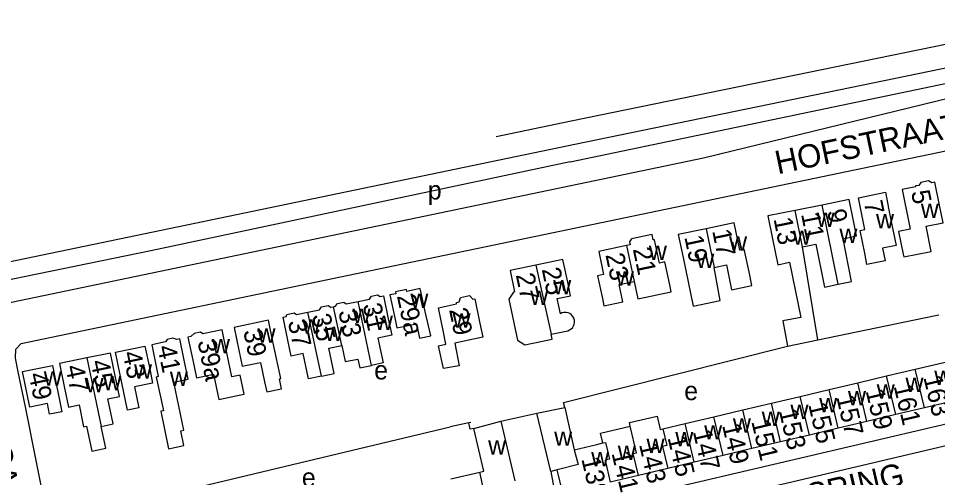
# Model space of a CAD drawing. Extents: x 163026 to 166241, y 382475 to 384501.
# Drawn here: x 164035.2 to 164232.4, y 384127.8 to 384226.4 of the extents above; entities that cross this region are included whole.
import ezdxf

# ---------------------------------------------------------------- set-up
doc = ezdxf.new("R2010")
doc.units = 0
for name, color, linetype in [('BLT_Basislijn', 7, 'Continuous'), ('BLT_Bebouwing', 7, 'Continuous'), ('BLT_Centroide', 7, 'Continuous'), ('BLT_Huisnummer', 7, 'Continuous'), ('BLT_Huisnummer_ tussenligend', 7, 'Continuous'), ('BLT_Onderverdeling_panden', 7, 'Continuous'), ('BLT_Spoorlijn', 7, 'Continuous'), ('BLT_Straatnaam', 7, 'Continuous')]:
    doc.layers.add(name, color=color, linetype=linetype)

msp = doc.modelspace()

# ---------------------------------------------------------------- linework, layer by layer
at = {"layer": 'BLT_Basislijn'}
for p, q in [((164152.1, 384143.91), (164200.2, 384156.04)), ((164152.39, 384142.84), (164152.1, 384143.91)), ((164138.72, 384139.93), (164146.41, 384141.66)), ((164041.64, 384118.16), (164127.83, 384138.74)), ((164151.07, 384119.92), (164236.93, 384140.04)), ((164149.43, 384129.14), (164151.07, 384119.92))]:
    msp.add_line(p, q, dxfattribs=at)
for points in [[(164153.55, 384195.58), (164243.98, 384214.46), (164247.92, 384214.05), (164263.66, 384217.55)], [(163900.11, 384137.3), (163905.37, 384138.71), (164182.17, 384196.48), (164249.9, 384212.98), (164253.88, 384212.82), (164257.32, 384211.62), (164261.05, 384208.36), (164262.81, 384205.4), (164265.99, 384192.34), (164268.94, 384175.29), (164269.89, 384164.18), (164270.1, 384149.11), (164272.14, 384146.86), (164275.23, 384146.44), (164277.11, 384147)], [(164041.64, 384118.16), (164036.68, 384143.01), (164035.15, 384150.54), (164034.58, 384153.44), (164034.61, 384155.37), (164035.79, 384156.58), (164112.52, 384172.6), (164235.89, 384198.32), (164241.09, 384199.14)], [(164153.55, 384195.58), (164063.6, 384176.49), (163969.43, 384157.19)], [(164206.72, 384157.42), (164231.95, 384162.6), (164232.65, 384162.76)], [(164046.47, 384095.37), (164046.9, 384094.29), (164048.09, 384092.84), (164049.85, 384092.25), (164052.21, 384092.19), (164083.95, 384099.3), (164253.63, 384139.27), (164258.18, 384142.14), (164259.86, 384145.55)], [(164132.89, 384138.36), (164132.12, 384138.19), (164131.84, 384139.58)]]:
    msp.add_lwpolyline(points, dxfattribs=at)
at = {"layer": 'BLT_Bebouwing'}
for p, q in [((164207.64, 384186.31), (164201.83, 384185.15)), ((164206.72, 384157.42), (164203.4, 384177.34)), ((164200.2, 384156.04), (164206.72, 384157.42)), ((164227.62, 384151.09), (164234.7, 384152.76)), ((164221.45, 384149.63), (164227.62, 384151.09)), ((164215.28, 384148.17), (164221.45, 384149.63)), ((164202.93, 384145.26), (164209.11, 384146.71)), ((164209.11, 384146.71), (164215.28, 384148.17)), ((164196.76, 384143.8), (164202.93, 384145.26)), ((164146.41, 384141.66), (164152.39, 384142.84)), ((164152.39, 384142.84), (164154.43, 384133.8)), ((164190.59, 384142.34), (164196.76, 384143.8)), ((164229.59, 384142.78), (164223.41, 384141.33)), ((164235.76, 384144.24), (164229.59, 384142.78)), ((164149.43, 384129.14), (164146.41, 384141.66)), ((164178.24, 384139.42), (164184.41, 384140.88)), ((164184.41, 384140.88), (164190.59, 384142.34)), ((164223.41, 384141.33), (164217.24, 384139.87)), ((164131.84, 384139.58), (164127.83, 384138.74)), ((164132.23, 384139.66), (164131.84, 384139.58)), ((164132.89, 384138.36), (164138.72, 384139.93)), ((164138.72, 384139.93), (164141.67, 384127.16)), ((164173.43, 384138.29), (164178.24, 384139.42)), ((164217.24, 384139.87), (164211.07, 384138.41)), ((164204.89, 384136.95), (164198.72, 384135.49)), ((164211.07, 384138.41), (164204.89, 384136.95)), ((164198.72, 384135.49), (164192.55, 384134.04)), ((164192.55, 384134.04), (164186.37, 384132.58)), ((164180.2, 384131.12), (164174.49, 384129.77)), ((164186.37, 384132.58), (164180.2, 384131.12)), ((164127.98, 384127.55), (164134.19, 384129.02)), ((164150.77, 384129.49), (164149.43, 384129.14)), ((164174.49, 384129.77), (164168.21, 384128.29)), ((164168.21, 384128.29), (164162.18, 384126.86))]:
    msp.add_line(p, q, dxfattribs=at)
for points in [[(164232.8, 384186.31), (164231.82, 384191.21), (164231.15, 384191.08), (164230.47, 384191.53), (164228.78, 384191.19), (164228.35, 384190.54), (164227.65, 384190.41), (164227.69, 384190.23), (164224.81, 384189.66), (164226.52, 384181.16), (164224.03, 384180.67), (164225.02, 384175.77), (164225.13, 384175.2), (164231.02, 384176.38), (164229.94, 384181.8), (164233.56, 384182.52), (164232.8, 384186.31)], [(164222.18, 384184.15), (164222.94, 384180.36), (164223.49, 384177.63), (164220.57, 384177.04), (164221.12, 384174.35), (164217.24, 384173.57), (164216.76, 384175.97), (164215.78, 384180.88), (164216.81, 384181.08), (164215.45, 384187.89), (164221.2, 384189.05), (164222.18, 384184.15)], [(164211.05, 384169.3), (164213.96, 384169.89), (164212.11, 384179.1), (164215.02, 384179.68), (164214.44, 384182.57), (164213.46, 384187.48), (164207.64, 384186.31)], [(164201.83, 384185.15), (164195.99, 384183.98), (164196.99, 384179.04), (164198.09, 384173.51), (164200.65, 384174.03), (164203.02, 384162.18), (164199.19, 384161.47), (164200.2, 384156.04)], [(164184.49, 384172.93), (164187.09, 384173.47), (164188.21, 384168.11), (164192.56, 384169.02), (164191.94, 384171.96), (164190.92, 384176.86), (164189.97, 384176.66), (164188.75, 384182.48), (164182.76, 384181.22)], [(164182.76, 384181.22), (164176.76, 384179.97), (164177.78, 384175.09), (164179.96, 384164.64), (164185.77, 384165.85), (164184.49, 384172.93)], [(164167.28, 384169.94), (164168.06, 384166.2), (164175.24, 384167.7), (164174.92, 384169.22), (164173.9, 384174.11), (164172.71, 384173.87), (164171.67, 384178.87), (164171.4, 384178.82), (164171.16, 384179.98), (164166.69, 384179.05), (164166.32, 384178.41), (164166.45, 384177.78), (164165.67, 384177.62)], [(164165.67, 384177.62), (164159.68, 384176.37), (164160.72, 384171.39), (164159.46, 384171.12), (164160.48, 384166.23), (164160.8, 384164.69), (164164.87, 384165.54), (164164.09, 384169.27), (164167.28, 384169.94)], [(164203.4, 384177.34), (164206.3, 384177.92), (164208.14, 384168.72), (164211.05, 384169.3)], [(164149.45, 384158.61), (164153.04, 384159.35), (164153.45, 384159.52), (164153.76, 384159.73), (164154.03, 384159.99), (164154.27, 384160.36), (164154.42, 384160.74), (164154.49, 384161.19), (164154.47, 384161.62), (164154.33, 384162.07), (164154.13, 384162.43), (164153.82, 384162.78), (164153.49, 384163.02), (164153.12, 384163.18), (164152.68, 384163.27), (164152.23, 384163.27), (164151.79, 384163.16), (164151.46, 384163), (164150.78, 384166.25), (164153.64, 384166.85), (164153.03, 384169.76), (164152.01, 384174.65), (164146.21, 384173.44)], [(164146.21, 384173.44), (164140.68, 384172.28), (164141.64, 384167.68), (164141.42, 384167.64), (164140.42, 384166.1), (164142.26, 384157.29), (164143.8, 384156.28), (164149.68, 384157.51), (164149.45, 384158.61)], [(164122.42, 384163.49), (164121.39, 384168.38), (164118.54, 384167.78), (164118.46, 384168.17), (164116.09, 384167.67), (164116.17, 384167.28), (164114.89, 384167.01), (164115.91, 384162.12), (164116.36, 384159.97), (164120.59, 384160.85), (164121.25, 384157.72), (164123.66, 384158.22), (164122.42, 384163.49)], [(164108.05, 384165.63), (164110.5, 384166.14), (164110.9, 384166.76), (164112.23, 384167.03), (164112.79, 384166.67), (164113.51, 384166.82), (164114.54, 384161.93), (164115.27, 384158.4), (164112.32, 384157.78), (164113.44, 384152.43), (164110.92, 384151.9)], [(164126.37, 384151.2), (164125.34, 384156.13), (164126.92, 384156.46), (164126.3, 384159.41), (164125.28, 384164.29), (164129.2, 384165.1), (164129.14, 384165.4), (164129.71, 384165.52), (164130.03, 384166.49), (164131.99, 384166.9), (164132.71, 384166.09), (164133.08, 384166.17), (164134.11, 384161.28), (164134.81, 384157.93), (164128.81, 384156.68), (164129.77, 384151.83), (164126.37, 384151.2)], [(164097.3, 384163.34), (164099.8, 384163.86), (164100.19, 384164.45), (164101.62, 384164.75), (164102.19, 384164.37), (164102.8, 384164.5)], [(164102.8, 384164.5), (164103.24, 384164.59), (164103.62, 384165.17), (164104.97, 384165.46), (164105.51, 384165.1), (164108.05, 384165.63)], [(164100.18, 384149.58), (164097.42, 384149), (164096.28, 384154.43), (164093.72, 384153.89), (164093, 384157.34), (164091.98, 384162.23), (164092.64, 384162.37), (164092.79, 384162.84), (164094.31, 384163.16), (164094.83, 384162.82), (164097.3, 384163.34)], [(164089.87, 384156.7), (164088.86, 384161.59), (164081.48, 384160.06), (164082.5, 384155.16), (164083.21, 384151.72), (164087.14, 384152.54), (164088.01, 384148.37), (164088.46, 384146.2), (164091.61, 384146.86), (164091.16, 384149.03), (164091.45, 384149.09), (164089.87, 384156.7)], [(164079.93, 384154.63), (164078.91, 384159.53), (164074.77, 384158.66), (164074.24, 384159.01), (164072.85, 384158.72), (164072.17, 384158.11), (164071.56, 384157.99), (164072.59, 384153.03), (164073.38, 384149.23), (164077.05, 384149.99), (164078.17, 384144.58), (164081.86, 384145.35), (164083.59, 384145.71), (164082.73, 384149.82), (164081, 384149.46), (164079.93, 384154.63)], [(164070.81, 384152.67), (164069.79, 384157.57), (164069.18, 384157.44), (164068.33, 384157.72), (164067.06, 384157.46), (164066.72, 384156.93), (164063.77, 384156.32), (164065.18, 384149.5), (164064.76, 384149.41), (164065.78, 384144.51), (164066.27, 384142.17), (164065.7, 384142.05), (164067.36, 384134), (164070.69, 384134.68), (164070.02, 384137.88), (164070.67, 384138.01), (164068.54, 384148.31), (164071.59, 384148.95), (164070.81, 384152.67)], [(164052.95, 384138.8), (164055.52, 384139.34), (164054.39, 384144.75), (164056.86, 384145.26), (164055.94, 384149.67), (164054.93, 384154.56), (164049.89, 384153.51)], [(164063.34, 384151.17), (164063.98, 384148.12), (164060.05, 384147.3), (164060.99, 384142.77), (164058.58, 384142.32), (164057.02, 384149.85), (164056, 384154.75), (164062.32, 384156.06), (164063.34, 384151.17)], [(164100.18, 384149.58), (164102.93, 384150.15), (164101.8, 384155.58), (164104.54, 384156.16)], [(164104.54, 384156.16), (164105.32, 384152.71), (164108.01, 384153.27), (164108.41, 384151.37), (164110.92, 384151.9)], [(164049.89, 384153.51), (164043.98, 384152.28), (164045, 384147.39), (164045.92, 384142.97), (164048.18, 384143.44), (164049.15, 384138.75), (164049.8, 384138.89), (164050.92, 384133.49), (164051.27, 384133.56), (164053.93, 384134.11), (164052.95, 384138.8)], [(164036.03, 384150.57), (164042.46, 384151.91), (164044.52, 384141.97), (164041.88, 384141.42), (164041.39, 384143.73), (164037.62, 384142.95), (164036.03, 384150.57)], [(164166.47, 384138.88), (164166.3, 384139.61), (164172.21, 384141), (164172.88, 384138.16), (164173.43, 384138.29)], [(164160.58, 384135.25), (164160.08, 384137.37), (164166.47, 384138.88)], [(164134.19, 384129.02), (164135.04, 384129.22), (164132.89, 384138.36)], [(164154.43, 384133.8), (164159.3, 384134.95), (164160.58, 384135.25)], [(164156.49, 384125.52), (164151.96, 384124.45), (164150.77, 384129.49)]]:
    msp.add_lwpolyline(points, dxfattribs=at)
at = {"layer": 'BLT_Onderverdeling_panden'}
for p, q in [((164211.05, 384169.3), (164207.64, 384186.31)), ((164203.4, 384177.34), (164201.83, 384185.15)), ((164182.76, 384181.22), (164184.49, 384172.93)), ((164165.67, 384177.62), (164167.28, 384169.94)), ((164146.21, 384173.44), (164149.45, 384158.61)), ((164104.54, 384156.16), (164102.8, 384164.5)), ((164110.92, 384151.9), (164108.05, 384165.63)), ((164100.18, 384149.58), (164097.3, 384163.34)), ((164049.89, 384153.51), (164052.95, 384138.8)), ((164229.59, 384142.78), (164227.62, 384151.09)), ((164223.41, 384141.33), (164221.45, 384149.63)), ((164211.07, 384138.41), (164209.11, 384146.71)), ((164217.24, 384139.87), (164215.28, 384148.17)), ((164204.89, 384136.95), (164202.93, 384145.26)), ((164198.72, 384135.49), (164196.76, 384143.8)), ((164186.37, 384132.58), (164184.41, 384140.88)), ((164192.55, 384134.04), (164190.59, 384142.34)), ((164180.2, 384131.12), (164178.24, 384139.42)), ((164134.99, 384125.37), (164134.19, 384129.02))]:
    msp.add_line(p, q, dxfattribs=at)
for points in [[(164168.21, 384128.29), (164167.11, 384132.99), (164167.82, 384133.16), (164166.47, 384138.88)], [(164173.43, 384138.29), (164174.28, 384134.68), (164173.38, 384134.47), (164174.49, 384129.77)], [(164160.58, 384135.25), (164161.12, 384135.38), (164161.97, 384131.78), (164161.07, 384131.56), (164162.18, 384126.86)], [(164154.43, 384133.8), (164155.26, 384130.64), (164150.77, 384129.49)]]:
    msp.add_lwpolyline(points, dxfattribs=at)
at = {"layer": 'BLT_Spoorlijn'}
for points in [[(164261.34, 384226.38), (164153.75, 384204.3)], [(164262.61, 384221.53), (164154.58, 384199.32)], [(164153.75, 384204.3), (164137.67, 384200.96)], [(164154.58, 384199.32), (163980.39, 384163.11)]]:
    msp.add_lwpolyline(points, dxfattribs=at)

# ---------------------------------------------------------------- texts
at = {"layer": 'BLT_Centroide'}
for s, p in [('p', (164123.01, 384187.51)), ('w', (164228.8, 384183.56)), ('w', (164206.44, 384181.64)), ('w', (164219.19, 384181.31)), ('w', (164201.36, 384177.78)), ('w', (164211.33, 384178.2)), ('w', (164187.66, 384176.5)), ('w', (164170.45, 384174.5)), ('w', (164180.62, 384172.78)), ('w', (164149.92, 384167.14)), ('w', (164163.38, 384169)), ('w', (164119.27, 384164.25)), ('w', (164144.98, 384164.86)), ('w', (164106.86, 384161)), ('w', (164111.66, 384159.48)), ('w', (164128.34, 384159.98)), ('w', (164096.08, 384158.73)), ('w', (164086.47, 384156.75)), ('w', (164100.92, 384157.16)), ('w', (164076.7, 384154.5)), ('w', (164040.62, 384147.55)), ('w', (164059.98, 384149.08)), ('w', (164067.67, 384147.5)), ('e', (164111.51, 384148.89)), ('w', (164231.69, 384147.67)), ('w', (164049.58, 384146.14)), ('w', (164053.38, 384146.58)), ('w', (164225.52, 384146.2)), ('e', (164178.03, 384144.45)), ('w', (164219.34, 384144.75)), ('w', (164207, 384141.83)), ('w', (164213.17, 384143.3)), ('w', (164200.83, 384140.38)), ('w', (164194.66, 384138.92)), ('w', (164182.31, 384136)), ('w', (164188.48, 384137.45)), ('w', (164150.12, 384134.64)), ('w', (164176.12, 384134.55)), ('w', (164135.95, 384132.77)), ('w', (164163.78, 384131.62)), ('w', (164169.95, 384133.08)), ('w', (164158.06, 384130.27)), ('e', (164095.99, 384125.87))]:
    msp.add_text(s, height=4, dxfattribs=at).set_placement(p)
at = {"layer": 'BLT_Huisnummer'}
for s, rotation, p in [('5', 281.3326, (164226.69, 384189.16)), ('7', 281.3326, (164216.55, 384186.93)), ('13', 281.33, (164197.18, 384183.34)), ('17', 281.8068, (164184.01, 384180.78)), ('19', 281.8068, (164178.05, 384179.46)), ('21', 281.8082, (164166.99, 384176.87)), ('23', 281.8069, (164161.12, 384175.64)), ('25', 281.8051, (164147.45, 384172.54)), ('27', 281.8054, (164141.88, 384171.33)), ('29a', 281.8066, (164116.37, 384166.82)), ('31', 281.8083, (164109.04, 384164.89)), ('29', 281.8087, (164127.56, 384163.87)), ('37', 281.8066, (164092.97, 384161.3)), ('39', 281.7603, (164083.4, 384159.29)), ('39a', 281.7502, (164073.58, 384157.05)), ('41', 281.7482, (164064.96, 384155.87)), ('45', 281.7594, (164050.64, 384152.73)), ('49', 281.7485, (164037.34, 384150)), ('163', 283.2879, (164229.34, 384149.34)), ('159', 283.2936, (164216.94, 384146.44)), ('155', 283.2936, (164204.62, 384143.51)), ('151', 283.2936, (164192.41, 384139.86)), ('147', 283.2936, (164179.87, 384137.69)), ('143', 283.2936, (164168.32, 384134.94)), ('139', 283.2936, (164155.94, 384131.83))]:
    msp.add_text(s, height=4, rotation=rotation, dxfattribs=at).set_placement(p)
at = {"layer": 'BLT_Huisnummer_ tussenligend'}
for s, rotation, p in [('11', 281.3326, (164203.09, 384184.39)), ('9', 281.3326, (164208.68, 384185.08)), ('35', 281.8083, (164098.14, 384162.62)), ('33', 281.8083, (164103.79, 384163.49)), ('43', 281.7482, (164057.5, 384154.59)), ('47', 281.7594, (164045.23, 384151.64)), ('161', 283.2936, (164222.95, 384147.47)), ('157', 283.2936, (164210.64, 384145.12)), ('153', 283.2936, (164198.33, 384142.15)), ('149', 283.2936, (164186.14, 384139.03)), ('145', 283.2936, (164174.44, 384136.4)), ('141', 283.2936, (164162.42, 384133.06))]:
    msp.add_text(s, height=4, rotation=rotation, dxfattribs=at).set_placement(p)
at = {"layer": 'BLT_Straatnaam'}
for s, rotation, p in [('HOFSTRAAT', 11.8754, (164198.1, 384192.9)), ('MERCATORSTRAAT', 281.2957, (164025.62, 384149.1)), ('KAARTMAKERSRING', 13.0805, (164160.12, 384111.02))]:
    msp.add_text(s, height=5, rotation=rotation, dxfattribs=at).set_placement(p)

doc.saveas('drawing.dxf')
